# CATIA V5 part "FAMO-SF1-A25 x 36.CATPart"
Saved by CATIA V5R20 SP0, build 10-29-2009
Part number: FAMO-SF1-A25 x 36
Definition: NONE
Nomenclature: FAMO-SF1-A25 x 36
Source: Unknown
Description: FAMO-SF1-A25 x 36
Bounding box of the stored display mesh (mm): x -13 to 23, y -22 to 22, z -22 to 22
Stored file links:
  C:\Users\Utente\Desktop\IO LAVORO\3D X SITO CF\X SITO\FAMO\FAMO-SF1-A25 x 36.CATPart
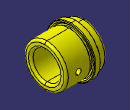
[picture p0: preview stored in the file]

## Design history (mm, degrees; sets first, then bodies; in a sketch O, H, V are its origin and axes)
Body1 "FAMO-SF1-A25 x 36" (main body)
  Solid1: solid without history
